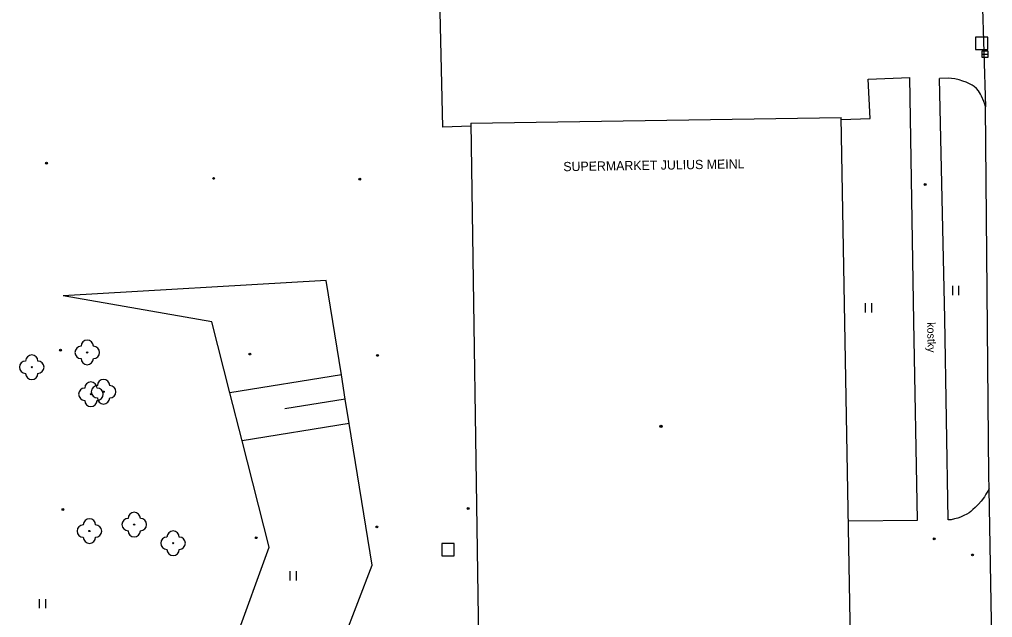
# Model space of a CAD drawing. Extents: x -641829 to -641525, y -1114855 to -1114359.
# Drawn here: x -641662 to -641583, y -1114485.6 to -1114437 of the extents above; entities that cross this region are included whole.
import ezdxf

# ---------------------------------------------------------------- set-up
doc = ezdxf.new("R2010")
doc.units = 0
for name, color, linetype in [('Vrstva 10', 7, 'Continuous'), ('Vrstva 11', 7, 'Continuous'), ('Vrstva 14', 7, 'Continuous'), ('Vrstva 15', 7, 'Continuous'), ('Vrstva 20', 7, 'Continuous'), ('Vrstva 22', 7, 'Continuous'), ('Vrstva 26', 7, 'Continuous'), ('Vrstva 27', 7, 'Continuous'), ('Vrstva 36', 7, 'Continuous'), ('Vrstva 39', 7, 'Continuous'), ('Vrstva 40', 7, 'Continuous'), ('Vrstva 41', 7, 'Continuous'), ('Vrstva 5', 7, 'Continuous')]:
    doc.layers.add(name, color=color, linetype=linetype)

msp = doc.modelspace()

# ---------------------------------------------------------------- linework, layer by layer
at = {"layer": 'Vrstva 10'}
for p, q in [((-641583.89, -1114432.83), (-641583.53, -1114444.1)), ((-641583.25, -1114474.03), (-641583.53, -1114444.1)), ((-641583.23, -1114475.12), (-641583.25, -1114474.03)), ((-641582.96, -1114491.51), (-641583.23, -1114475.12))]:
    msp.add_line(p, q, dxfattribs=at)
at = {"layer": 'Vrstva 11'}
for p, q in [((-641627.59, -1114445.77), (-641628.37, -1114413.4)), ((-641593.06, -1114441.86), (-641589.67, -1114441.73)), ((-641592.89, -1114445.05), (-641593.06, -1114441.86)), ((-641589.35, -1114461.54), (-641589.67, -1114441.73)), ((-641586.51, -1114441.78), (-641587.28, -1114441.82)), ((-641586.84, -1114461.29), (-641587.28, -1114441.82)), ((-641595.25, -1114445.14), (-641592.89, -1114445.05)), ((-641625.33, -1114445.68), (-641627.59, -1114445.77)), ((-641589.06, -1114477.67), (-641589.35, -1114461.54)), ((-641586.55, -1114477.65), (-641586.84, -1114461.29)), ((-641583.23, -1114475.12), (-641583.34, -1114475.32)), ((-641583.62, -1114475.76), (-641583.89, -1114476.12)), ((-641583.5, -1114475.57), (-641583.62, -1114475.76)), ((-641583.34, -1114475.32), (-641583.5, -1114475.57)), ((-641584.36, -1114476.63), (-641584.55, -1114476.81)), ((-641584.1, -1114476.37), (-641584.36, -1114476.63)), ((-641583.89, -1114476.12), (-641584.1, -1114476.37)), ((-641585.79, -1114477.51), (-641586.06, -1114477.57)), ((-641585.56, -1114477.43), (-641585.79, -1114477.51)), ((-641585.28, -1114477.3), (-641585.56, -1114477.43)), ((-641585.05, -1114477.17), (-641585.28, -1114477.3)), ((-641584.87, -1114477.07), (-641585.05, -1114477.17)), ((-641584.73, -1114476.96), (-641584.87, -1114477.07)), ((-641584.55, -1114476.81), (-641584.73, -1114476.96)), ((-641594.67, -1114477.71), (-641589.06, -1114477.67)), ((-641586.33, -1114477.63), (-641586.55, -1114477.65)), ((-641586.06, -1114477.57), (-641586.33, -1114477.63))]:
    msp.add_line(p, q, dxfattribs=at)
for points in [[(-641584.45, -1114442.45), (-641584.62, -1114442.35), (-641584.84, -1114442.24), (-641585.11, -1114442.12), (-641585.37, -1114442.02), (-641585.67, -1114441.93), (-641586.01, -1114441.85), (-641586.3, -1114441.81), (-641586.51, -1114441.78)], [(-641583.53, -1114444.1), (-641583.58, -1114443.9), (-641583.66, -1114443.68), (-641583.85, -1114443.26), (-641583.94, -1114443.08), (-641584.09, -1114442.82), (-641584.26, -1114442.62), (-641584.45, -1114442.45)]]:
    msp.add_lwpolyline(points, dxfattribs=at)
at = {"layer": 'Vrstva 14'}
for p, q in [((-641637.07, -1114458.21), (-641658.42, -1114459.45)), ((-641635.84, -1114465.88), (-641637.07, -1114458.21)), ((-641646.36, -1114461.56), (-641658.42, -1114459.45)), ((-641644.89, -1114467.34), (-641646.36, -1114461.56)), ((-641635.52, -1114467.85), (-641635.84, -1114465.88)), ((-641643.9, -1114471.23), (-641644.89, -1114467.34)), ((-641635.2, -1114469.83), (-641635.52, -1114467.85)), ((-641633.35, -1114481.33), (-641635.2, -1114469.83)), ((-641641.7, -1114479.87), (-641643.9, -1114471.23)), ((-641649.59, -1114501.58), (-641641.7, -1114479.87)), ((-641643.19, -1114506.99), (-641633.35, -1114481.33))]:
    msp.add_line(p, q, dxfattribs=at)
at = {"layer": 'Vrstva 15'}
for p, q in [((-641635.84, -1114465.88), (-641644.89, -1114467.34)), ((-641635.52, -1114467.85), (-641640.44, -1114468.64)), ((-641635.2, -1114469.83), (-641643.9, -1114471.23))]:
    msp.add_line(p, q, dxfattribs=at)
at = {"layer": 'Vrstva 20'}
for centre, radius in [((-641659.78, -1114448.69), 0.075), ((-641659.78, -1114448.69), 0.0204), ((-641646.21, -1114449.92), 0.075), ((-641646.21, -1114449.92), 0.0204), ((-641634.35, -1114449.98), 0.075), ((-641634.35, -1114449.98), 0.0204), ((-641588.43, -1114450.42), 0.075), ((-641588.43, -1114450.42), 0.0204), ((-641658.65, -1114463.87), 0.075), ((-641658.65, -1114463.87), 0.0204), ((-641643.27, -1114464.18), 0.075), ((-641643.27, -1114464.18), 0.0204), ((-641632.9, -1114464.29), 0.075), ((-641632.9, -1114464.29), 0.0204), ((-641658.45, -1114476.8), 0.075), ((-641625.54, -1114476.72), 0.075), ((-641625.54, -1114476.72), 0.0204), ((-641658.45, -1114476.8), 0.0204), ((-641632.96, -1114478.22), 0.075), ((-641632.96, -1114478.22), 0.0204), ((-641642.75, -1114479.09), 0.075), ((-641642.75, -1114479.09), 0.0204), ((-641587.69, -1114479.19), 0.075), ((-641587.69, -1114479.19), 0.0204), ((-641584.58, -1114480.49), 0.075), ((-641584.58, -1114480.49), 0.0204)]:
    msp.add_circle(centre, radius, dxfattribs=at)
at = {"layer": 'Vrstva 22'}
for centre in [(-641656.48, -1114464.05), (-641660.98, -1114465.25), (-641655.15, -1114467.24), (-641656.18, -1114467.44), (-641652.66, -1114478.03), (-641656.3, -1114478.55), (-641649.5, -1114479.54)]:
    msp.add_circle(centre, 0.05, dxfattribs=at)
for centre, start, end in [((-641656.48, -1114463.55), 0, 180), ((-641656.98, -1114464.05), 90, 270), ((-641655.98, -1114464.05), 270, 90), ((-641661.48, -1114465.25), 90, 270), ((-641660.98, -1114464.75), 0, 180), ((-641660.48, -1114465.25), 270, 90), ((-641656.48, -1114464.55), 180, 0), ((-641660.98, -1114465.75), 180, 0), ((-641656.18, -1114466.94), 0, 180), ((-641655.15, -1114466.74), 0, 180), ((-641656.68, -1114467.44), 90, 270), ((-641655.65, -1114467.24), 90, 270), ((-641655.68, -1114467.44), 270, 90), ((-641654.65, -1114467.24), 270, 90), ((-641656.18, -1114467.94), 180, 0), ((-641655.15, -1114467.74), 180, 0), ((-641653.16, -1114478.03), 90, 270), ((-641652.66, -1114477.53), 0, 180), ((-641652.16, -1114478.03), 270, 90), ((-641656.8, -1114478.55), 90, 270), ((-641656.3, -1114478.05), 0, 180), ((-641655.8, -1114478.55), 270, 90), ((-641656.3, -1114479.05), 180, 0), ((-641652.66, -1114478.53), 180, 0), ((-641650, -1114479.54), 90, 270), ((-641649.5, -1114479.04), 0, 180), ((-641649, -1114479.54), 270, 90), ((-641649.5, -1114480.04), 180, 0)]:
    msp.add_arc(centre, 0.5, start, end, dxfattribs=at)
at = {"layer": 'Vrstva 26'}
for points in [[(-641583.35, -1114438.45), (-641584.35, -1114438.45), (-641584.35, -1114439.45), (-641583.35, -1114439.45)], [(-641627.68, -1114480.56), (-641626.68, -1114480.56), (-641626.68, -1114479.56), (-641627.68, -1114479.56)]]:
    msp.add_lwpolyline(points, close=True, dxfattribs=at)
at = {"layer": 'Vrstva 27'}
msp.add_line((-641583.82, -1114439.84), (-641583.32, -1114439.84), dxfattribs=at)
msp.add_lwpolyline([(-641583.82, -1114440.09), (-641583.32, -1114440.09), (-641583.32, -1114439.59), (-641583.82, -1114439.59)], close=True, dxfattribs=at)
at = {"layer": 'Vrstva 36'}
for p, q in [((-641586.184, -1114459.394), (-641586.184, -1114458.642)), ((-641585.684, -1114459.394), (-641585.684, -1114458.642)), ((-641593.274, -1114460.812), (-641593.274, -1114460.064)), ((-641592.774, -1114460.812), (-641592.774, -1114460.064)), ((-641639.984, -1114482.562), (-641639.984, -1114481.814)), ((-641639.484, -1114482.562), (-641639.484, -1114481.814)), ((-641660.344, -1114484.824), (-641660.344, -1114484.072)), ((-641659.844, -1114484.824), (-641659.844, -1114484.072))]:
    msp.add_line(p, q, dxfattribs=at)
at = {"layer": 'Vrstva 39'}
for radius in [0.09, 0.0398]:
    msp.add_circle((-641609.89, -1114470.05), radius, dxfattribs=at)
at = {"layer": 'Vrstva 5'}
for p, q in [((-641625.33, -1114445.45), (-641595.25, -1114444.98)), ((-641594.4, -1114493.03), (-641595.25, -1114444.98)), ((-641625.33, -1114445.45), (-641624.57, -1114496.72))]:
    msp.add_line(p, q, dxfattribs=at)

# ---------------------------------------------------------------- texts
at = {"layer": 'Vrstva 40'}
msp.add_text('kostky', height=0.6499, rotation=271.03001, dxfattribs=at).set_placement((-641588.27, -1114461.6))
at = {"layer": 'Vrstva 41'}
msp.add_text('SUPERMARKET JULIUS MEINL', height=0.75, rotation=0.89517, dxfattribs=at).set_placement((-641617.81, -1114449.34))

doc.saveas('drawing.dxf')
